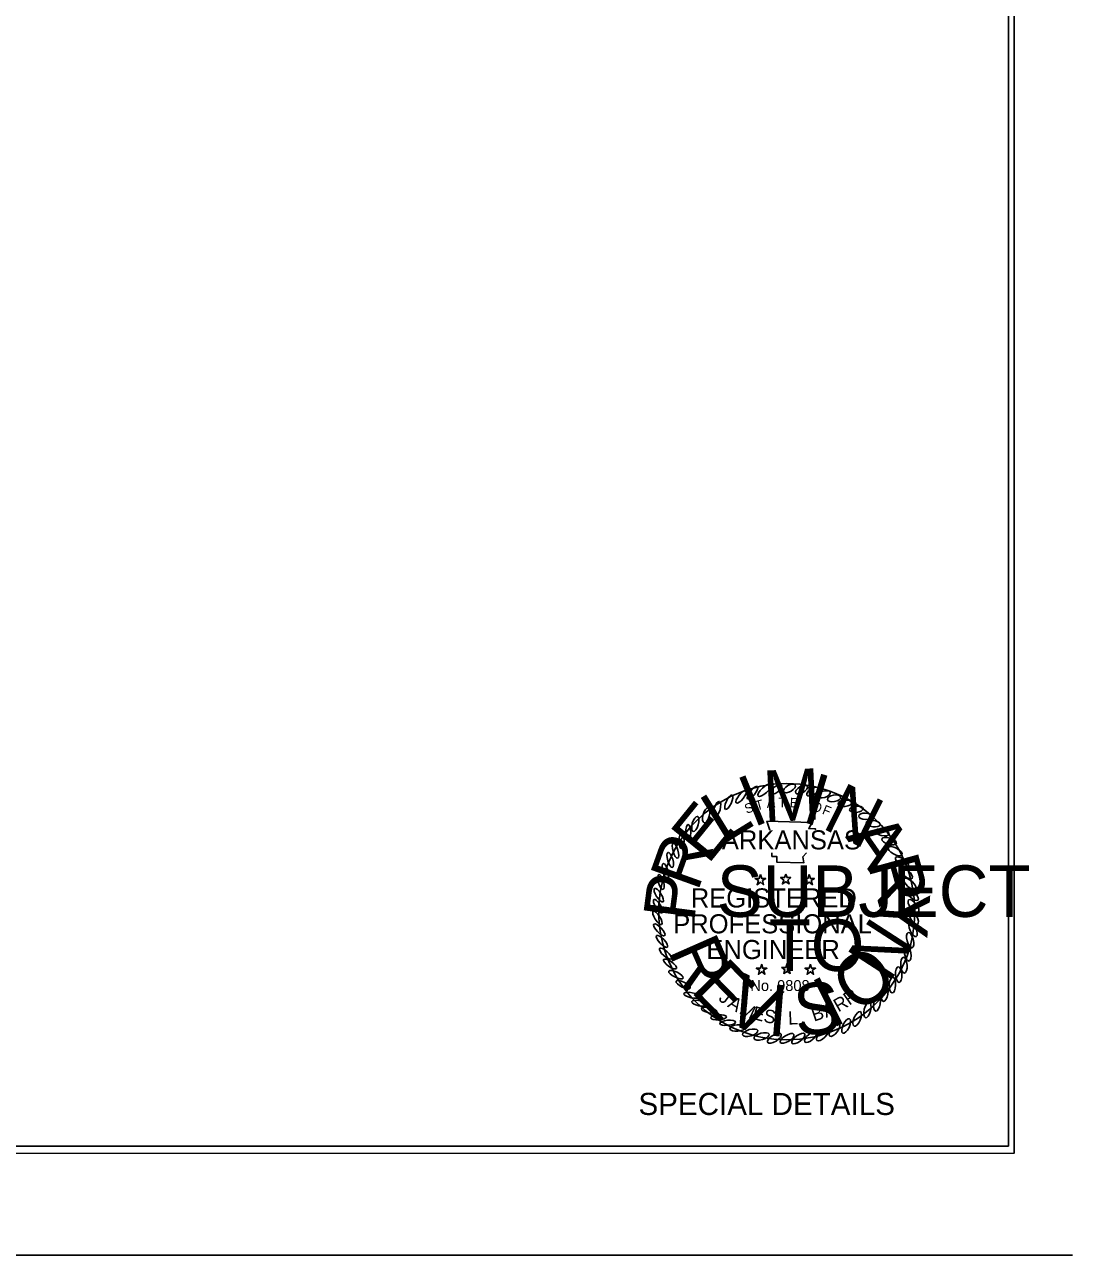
# Model space of a CAD drawing. Extents: x 714919 to 718439, y 1619644 to 1621844.
# Drawn here: x 717682 to 718439, y 1619644 to 1620534 of the extents above; entities that cross this region are included whole.
import ezdxf

# ---------------------------------------------------------------- set-up
doc = ezdxf.new("R2010")
doc.units = 0
for name, color, linetype in [('R_Border', 7, 'Continuous'), ('R_Border Notes', 7, 'Continuous'), ('R_Border PE', 7, 'Continuous'), ('R_Border Prem', 7, 'Continuous'), ('R_No Plot', 7, 'Continuous')]:
    doc.layers.add(name, color=color, linetype=linetype)

msp = doc.modelspace()

# ---------------------------------------------------------------- linework, layer by layer
at = {"layer": 'R_Border'}
for p, q in [((718393.18, 1619722.46), (718393.11, 1621777.06)), ((718393.18, 1619722.46), (715231.18, 1619722.46)), ((714919.08, 1619643.55), (718439.28, 1619643.76))]:
    msp.add_line(p, q, dxfattribs=at)
at = {"layer": 'R_Border PE'}
for points in [[(718220.5, 1619951.05), (718218.4, 1619957.55), (718251, 1619956.65), (718248.6, 1619952.25), (718253.6, 1619951.95), (718253.3, 1619951.35)], [(718247.1, 1619934.75), (718244.4, 1619931.85), (718245, 1619927.35), (718225.5, 1619927.95), (718225.5, 1619932.15), (718222, 1619932.15), (718222, 1619934.75)]]:
    msp.add_lwpolyline(points, dxfattribs=at)
for points in [[(718213.7, 1619919.05), (718214.6, 1619916.15), (718217.5, 1619916.15), (718215.1, 1619914.65), (718216, 1619911.65), (718213.7, 1619913.45), (718211.3, 1619911.65), (718212.2, 1619914.65), (718209.8, 1619916.15), (718212.8, 1619916.15)], [(718232, 1619919.35), (718232.9, 1619916.75), (718235.6, 1619916.75), (718233.5, 1619914.95), (718234.4, 1619912.25), (718232, 1619913.75), (718229.6, 1619912.25), (718230.5, 1619914.95), (718228.2, 1619916.75), (718231.1, 1619916.75)], [(718248.9, 1619919.05), (718249.8, 1619916.15), (718252.7, 1619916.15), (718250.4, 1619914.65), (718251.3, 1619911.65), (718248.9, 1619913.45), (718246.5, 1619911.65), (718247.4, 1619914.65), (718245, 1619916.15), (718248, 1619916.15)], [(718214.6, 1619854.25), (718215.4, 1619851.25), (718218.4, 1619851.25), (718216, 1619849.85), (718216.9, 1619846.85), (718214.6, 1619848.65), (718212.2, 1619846.85), (718213.1, 1619849.85), (718210.7, 1619851.25), (718213.7, 1619851.25)], [(718232.9, 1619854.55), (718233.8, 1619851.85), (718236.5, 1619851.85), (718234.1, 1619850.15), (718235.3, 1619847.45), (718232.9, 1619848.95), (718230.5, 1619847.45), (718231.4, 1619850.15), (718229.1, 1619851.85), (718232, 1619851.85)], [(718249.8, 1619854.25), (718250.7, 1619851.25), (718253.6, 1619851.25), (718251.3, 1619849.85), (718252.1, 1619846.85), (718249.8, 1619848.65), (718247.4, 1619846.85), (718248.3, 1619849.85), (718245.9, 1619851.25), (718248.9, 1619851.25)]]:
    msp.add_lwpolyline(points, close=True, dxfattribs=at)
for centre, major_axis, ratio in [((718190.77, 1619971.26), (-2.46, -5.15), 0.329518), ((718199.75, 1619975.21), (-3.58, -4.44), 0.329518), ((718207.89, 1619978.15), (-3.64, -4.4), 0.329518), ((718216.62, 1619979.96), (-4.59, -4.21), 0.348728), ((718224.99, 1619980.48), (-3.87, -3.02), 0.44237), ((718234.67, 1619981.29), (-4.21, -2.45), 0.475469), ((718243.37, 1619980.41), (-4.21, -2.45), 0.475469), ((718251.49, 1619978.94), (-4.21, -2.45), 0.475469), ((718259.44, 1619976.99), (-4.64, -1.48), 0.475469), ((718266.9, 1619974.12), (-4.79, -0.89), 0.475469), ((718182.4, 1619966.37), (-1.53, -5.49), 0.375751), ((718274.74, 1619970.56), (-4.85, -0.42), 0.475469), ((718283.06, 1619966.25), (-4.85, -0.42), 0.475469), ((718166.56, 1619955.54), (-1.53, -5.49), 0.391724), ((718174.48, 1619961.83), (-1.53, -5.49), 0.394697), ((718289.66, 1619961.11), (-4.87, 0.11), 0.475469), ((718161.4, 1619949.46), (0, -5.7), 0.322879), ((718295.29, 1619955.8), (-5.09, 0.7), 0.451028), ((718301.59, 1619949.47), (-5.17, 1.18), 0.436264), ((718152.23, 1619936.2), (1.57, -5.48), 0.322879), ((718156.62, 1619943.42), (0, -5.7), 0.322879), ((718306.78, 1619943.1), (-5.3, 1.59), 0.418512), ((718148.46, 1619929.53), (1.57, -5.48), 0.322879), ((718311.04, 1619935.92), (-4.99, 2.77), 0.40589), ((718316.06, 1619928), (-4.66, 3.28), 0.40589), ((718144.94, 1619921.6), (1.57, -5.48), 0.322879), ((718319.15, 1619920.01), (-4.3, 3.75), 0.40589), ((718141.8, 1619913.55), (1.57, -5.48), 0.322879), ((718321.79, 1619912.18), (-4.3, 3.75), 0.40589), ((718140.18, 1619904.11), (3.04, -4.83), 0.322879), ((718323.51, 1619904.52), (-4.1, 3.96), 0.40589), ((718139.68, 1619896.06), (3.04, -4.83), 0.322879), ((718324.37, 1619896.19), (-3.5, 4.5), 0.40589), ((718139.17, 1619887.63), (3.04, -4.83), 0.322879), ((718324.53, 1619887.91), (-2.77, 4.99), 0.40589), ((718140.57, 1619878.95), (3.92, -4.14), 0.322879), ((718324.02, 1619879.39), (-2.3, 5.22), 0.40589), ((718142.45, 1619870.65), (3.92, -4.14), 0.322879), ((718322.01, 1619871.55), (-1.48, 5.51), 0.40589), ((718145, 1619861.81), (4.29, -3.76), 0.322879), ((718320.21, 1619862.06), (-1.02, 5.61), 0.40589), ((718148.34, 1619854.29), (4.67, -3.27), 0.322879), ((718313.65, 1619846.63), (-0.33, 5.69), 0.40589), ((718317.42, 1619853.43), (-0.33, 5.69), 0.40589), ((718152.57, 1619846.61), (5.13, -2.49), 0.322879), ((718309.15, 1619839.04), (0.27, 5.7), 0.40589), ((718157.85, 1619839.31), (5.13, -2.49), 0.322879), ((718303.5, 1619832.87), (0.91, 5.63), 0.40589), ((718163.89, 1619831.68), (5.58, -1.19), 0.322879), ((718169.55, 1619825.89), (5.58, -1.19), 0.322879), ((718291.05, 1619820.98), (1.36, 5.54), 0.40589), ((718297.96, 1619825.83), (0.91, 5.63), 0.40589), ((718176.6, 1619820.85), (5.58, -1.19), 0.322879), ((718183.41, 1619815.7), (5.68, 0.48), 0.322879), ((718283.7, 1619814.58), (2.26, 5.24), 0.40589), ((718190.07, 1619811.79), (5.68, 0.48), 0.322879), ((718197.24, 1619808.02), (5.68, 0.48), 0.40589), ((718206.24, 1619804.59), (5.5, 1.52), 0.40589), ((718258.61, 1619802.96), (4.08, 3.98), 0.40589), ((718267.27, 1619806.71), (3.39, 4.59), 0.40589), ((718275.66, 1619809.47), (2.43, 5.16), 0.40589), ((718214.54, 1619801.95), (5.5, 1.52), 0.40589), ((718223.78, 1619800.58), (4.91, 2.91), 0.40589), ((718232.96, 1619800.45), (4.91, 2.91), 0.40589), ((718241.06, 1619800.38), (4.63, 3.33), 0.40589), ((718250.13, 1619801.6), (4.36, 3.68), 0.40589)]:
    msp.add_ellipse(centre, major_axis=major_axis, ratio=ratio, dxfattribs=at)
at = {"layer": 'R_Border Prem'}
msp.add_circle((718232.72, 1619892.13), 92.59, dxfattribs=at)
at = {"layer": 'R_No Plot'}
msp.add_lwpolyline([(715227.23, 1619717.26), (718397.13, 1619717.36), (718397.16, 1621782.46), (715227.06, 1621782.26)], close=True, dxfattribs=at)

# ---------------------------------------------------------------- texts
at = {"layer": 'R_Border Notes'}
msp.add_text('SPECIAL DETAILS', height=16, rotation=359.99837, dxfattribs=at).set_placement((718125.45, 1619745.09))
at = {"layer": 'R_Border PE'}
for s, height, rotation, p in [('S', 6.91, 19.58318, (718203.6, 1619962.85)), ('T', 6.91, 14.96327, (718211, 1619965.25)), ('A', 6.91, 5.72345, (718218.4, 1619967.05)), ('T', 6.91, 1.10354, (718226.7, 1619967.65)), ('E', 6.91, 356.48363, (718234.7, 1619967.65)), ('O', 6.91, 342.62389, (718250.1, 1619965.55)), ('F', 6.91, 338.00398, (718257.8, 1619963.15)), ('ARKANSAS', 13.814, 0.00182, (718185.8, 1619937.15)), ('REGISTERED', 13.814, 0.00182, (718163.3, 1619895.15)), ('PROFESSIONAL', 13.8138, 0.00182, (718150.6, 1619876.45)), ('ENGINEER', 13.814, 0.00182, (718174.6, 1619857.85)), ('J', 9.6, 322.41851, (718182.8, 1619828.45)), ('No. 9808', 7.892, 0.00182, (718206.4, 1619834.75)), ('R', 9.6, 35.22374, (718277.9, 1619824.05)), ('A', 9.6, 328.01891, (718189.3, 1619823.65)), ('M', 9.6, 333.61931, (718197.6, 1619818.85)), ('A', 9.6, 24.02294, (718261.2, 1619815.25)), ('R', 9.6, 29.62334, (718270, 1619819.25)), ('E', 9.6, 344.82012, (718207.1, 1619814.75)), ('S', 9.6, 350.42052, (718215.5, 1619812.35)), ('L', 9.6, 1.62133, (718233.8, 1619810.45)), ('B', 9.6, 18.42253, (718252.4, 1619812.55)), ('.', 9.6, 7.22173, (718242.7, 1619811.05))]:
    msp.add_text(s, height=height, rotation=rotation, dxfattribs=at).set_placement(p)
at = {"layer": 'R_Border Prem'}
for s, rotation, p in [('M', 2.69611, (718216.3, 1619956.85)), ('I', 22.01235, (718208.2, 1619952.75)), ('I', 343.37988, (718242.6, 1619957.45)), ('L', 31.67047, (718186.6, 1619940.55)), ('N', 333.72176, (718257.2, 1619952.95)), ('E', 50.9867, (718175.6, 1619925.55)), ('A', 304.74741, (718274.7, 1619946.35)), ('R', 70.30294, (718168.2, 1619905.95)), ('R', 285.43117, (718290.8, 1619927.55)), ('SUBJECT', 0.00182, (718182.1, 1619888.35)), ('P', 82.6107, (718165.7, 1619884.25)), ('Y', 266.11494, (718299.4, 1619907.55)), ('TO', 0.00182, (718219.7, 1619849.25)), ('N', 57.13957, (718306.4, 1619839.65)), ('R', 293.76569, (718146.4, 1619863.95)), ('O', 36.57726, (718283.7, 1619817.45)), ('E', 314.328, (718162.4, 1619834.75)), ('V', 334.89032, (718185.5, 1619814.45)), ('I', 26.2961, (718264.8, 1619807.15)), ('I', 355.45263, (718218.3, 1619802.65)), ('S', 5.73379, (718239.8, 1619802.05))]:
    msp.add_text(s, height=37.24, rotation=rotation, dxfattribs=at).set_placement(p)

doc.saveas('drawing.dxf')
